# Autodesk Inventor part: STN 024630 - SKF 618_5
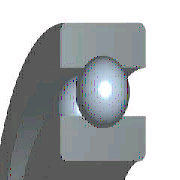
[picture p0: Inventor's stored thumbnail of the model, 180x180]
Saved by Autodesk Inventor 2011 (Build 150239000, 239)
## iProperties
IsCustomPart: 1
Created: 2007-02
Part Number: STN 024630 - SKF 618_5
Material: Steel, Mild
Description: Single row ball bearings
Document SubType Name: Modeling
Standard: STN 024630 SKF
Designer: Autodesk, Inc.
Standards Organization: STN
Language: en-US
Size Designation: SKF 618/5
Categories: <MemberInstance><Categories><Category DisplayName="Shaft Parts" InternalName="7f7aeb1f-a693-4053-b835-cee3144e0d98" Mnemonic="SHFT"><Category DisplayName="Beari
Density: 7.86 g/cm^3
Mass: 1.15893 g
Surface Area: 4.73523 cm^2
Volume: 0.147447 cm^3
Author: Autodesk, Inc.
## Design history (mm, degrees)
node "Sketch1"
node "WorkPoint1"
node "WorkAxis1"
node "WorkPlane3"
node "WorkPlane4"
node "Sketch4"
node "WorkPoint2"
pattern_circular "PolarArray1" dims "d17" = 70.66667 (= msp_pocet), angle "d19" = 360 deg
fillet "Fillet1" dims "d20" = 0.15 (= r)
body "Solid1"
revolve "Revolution1" stored, may be unused: angle "d6" = 360 deg
revolve "Revolution2" stored, may be unused: angle "d10" = 360 deg
revolve "Revolution3" stored, may be unused: angle "d16" = 360 deg
sketch "Sketch2"
  geometry: L1 (2.5, 3)-(5.5, 3); L2 (2.5, 0)-(2.5, 3); L3 (5.5, 0)-(2.5, 0); L4 (5.5, 3)-(5.5, 0); L5 (0, 0)-(0, 20); L6 (0, 0)-(0, 20); L7 (-1.1, 0)-(6.6, 0) reference
  constraints: 12 end point, 3 vertical, 2 horizontal, 1 collinear, 1 other
  dimensions: "d1" = 5 diameter of L1.start L5 (= Diam); "d3" = 11 diameter of L1.end L5 (= DD); "d5" = 3 distance of L2.start L1.start (= msp_mdtd2)
sketch "Sketch3"
  geometry: L1 (4.54, 3)-(4.54, 2.22); L2 (3.46, 3)-(4.54, 3); L3 (3.46, 2.22)-(3.46, 3); L4 (3.46, 0)-(3.46, 0.78); L5 (4.54, 0)-(3.46, 0); L6 (4.54, 0.78)-(4.54, 0); L7 (5.5, 0)-(-5.5, 0) reference; L8 (5.5, 3)-(-5.5, 3) reference; L9 (0, -42.29)-(0, 61.29); L10 (0, 82.007)-(0, -63.007) reference; A1 r 0.9 centre (4, 1.5) between (4.54, 0.78) and (4.54, 2.22); A2 r 0.9 centre (4, 1.5) between (3.46, 2.22) and (3.46, 0.78)
  constraints: 14 end point, 4 collinear, 4 point on circle, 4 vertical, 2 centre point, 2 concentric, 2 horizontal, 2 point on line
  dimensions: "d9" = 1.8 diameter of A1 (= msp_mdtd6); "d21" = 3.46 distance between parallel lines of L9 L4 (= 0.5 x msp_d1); "d22" = 4 distance from line of L9 A1.centre (= 0.5 x msp_ds); "d23" = 4.54 distance between parallel lines of L9 L6 (= 0.5 x msp_dd1)
sketch "Sketch5"
  geometry: L1 (4, 0.6)-(4, 2.4); L2 (4.54, 0)-(-4.54, 0) reference; L3 (4, 0.6)-(4, 2.4); A1 r 0.9 centre (4, 1.5) between (4, 0.6) and (4, 2.4); A2 r 0.9 centre (4, 1.5) between (4.54, 0.78) and (4.54, 2.22) reference
  constraints: 4 end point, 2 point on circle, 1 centre point, 1 concentric, 1 vertical
  dimensions: "d13" = 0 horizontal distance of A1.centre L1.start; "d15" = 1.8001 diameter of A1 (computed from msp_mdtd6)
other parameters: "Diam" = 5 [user parameter; used in 3 equation terms], "DD" = 11 [user parameter; used in 3 equation terms], "B" = 3 [user parameter; used in 1 equation term], "r" = 0.15 [user parameter; used in 1 equation term], "msp_ds" = 8 (= 0.5 x Diam + 0.5 x DD) [user parameter; used in 5 equation terms], "msp_d0" = 1.8 (= -0.3 x Diam + 0.3 x DD) [user parameter; used in 4 equation terms], "msp_d1" = 6.92 (= msp_ds - 0.6 x msp_d0) [user parameter; used in 1 equation term], "msp_dd1" = 9.08 (= msp_ds + 0.6 x msp_d0) [user parameter; used in 1 equation term], "msp_pom" = 12 (= 1.5 x msp_ds) [user parameter; used in 1 equation term], "msp_mdtd2" = 3 (= B) [user parameter; used in 3 equation terms], "msp_mdtd4" = 8 (= msp_ds) [user parameter], "msp_mdtd6" = 1.8 (= msp_d0) [user parameter; used in 2 equation terms], "msp_mdtd7" = 1.5 (= 0.5 x msp_mdtd2) [user parameter], "msp_pocet" = 70.66667 (computed from msp_d0, msp_pom) [user parameter; used in 1 equation term], "d2" = 72 (derived), "d4" = 19 (derived), "d7" = 0, "d8" = 15.6 (derived), "d11" = -3 (computed from msp_mdtd2), "d12" = 0 (derived), "d14" = 15.6001 (derived), "d26" = 0, "d27" = 0, "d28" = 0, "d29" = 0, "d30" = 0
